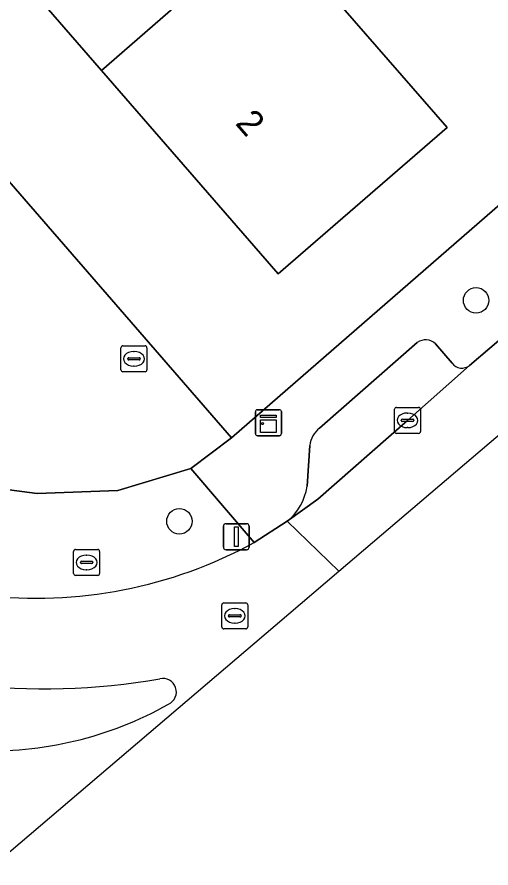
# Model space of a CAD drawing. Extents: x 155887 to 156869, y 383880 to 384678.
# Drawn here: x 156395.65 to 156413.9, y 383945.21 to 383977.95 of the extents above; entities that cross this region are included whole.
import ezdxf

# ---------------------------------------------------------------- set-up
doc = ezdxf.new("R2010")
doc.units = 0
for name, color, linetype in [('IMGEO_Berm_groen', 7, 'Continuous'), ('IMGEO_Boom', 7, 'Continuous'), ('IMGEO_Brandkraan', 7, 'Continuous'), ('IMGEO_Erf', 7, 'Continuous'), ('IMGEO_Kast', 7, 'Continuous'), ('IMGEO_Kolk', 7, 'Continuous'), ('IMGEO_Lichtmast', 7, 'Continuous'), ('IMGEO_Pand', 7, 'Continuous'), ('IMGEO_Pand_nummerreeks', 7, 'Continuous'), ('IMGEO_Parkeervlak_open', 7, 'Continuous'), ('IMGEO_Rijbaan_lokaal_gesloten', 7, 'Continuous'), ('IMGEO_Rioolput', 7, 'Continuous'), ('IMGEO_Verkeerseiland_open', 7, 'Continuous'), ('IMGEO_Voetpad_open', 7, 'Continuous')]:
    doc.layers.add(name, color=color, linetype=linetype)

msp = doc.modelspace()

# ---------------------------------------------------------------- linework, layer by layer
at = {"layer": 'IMGEO_Berm_groen'}
msp.add_lwpolyline([(156404.777, 383957.73), (156402.343, 383960.577), (156399.536, 383959.735), (156396.435, 383959.619), (156384.17, 383961.221), (156383.842, 383958.663), (156383.701, 383957.674)], dxfattribs=at)
msp.add_arc((156396.408, 383972.994), 17.408, 263.2684, 298.7369, dxfattribs=at)
at = {"layer": 'IMGEO_Boom'}
for centre in [(156413.326, 383967.047), (156401.904, 383958.547)]:
    msp.add_circle(centre, 0.489, dxfattribs=at)
at = {"layer": 'IMGEO_Brandkraan'}
for p, q in [((156399.655, 383964.372), (156399.655, 383965.224)), ((156399.73, 383965.298), (156400.582, 383965.298)), ((156400.656, 383965.224), (156400.656, 383964.372)), ((156399.957, 383964.841), (156400.355, 383964.841)), ((156400.143, 383965.078), (156400.168, 383965.078)), ((156399.914, 383964.792), (156399.914, 383964.804)), ((156400.352, 383964.755), (156399.954, 383964.755)), ((156400.166, 383964.518), (156400.141, 383964.518)), ((156400.398, 383964.804), (156400.398, 383964.792)), ((156400.582, 383964.298), (156399.73, 383964.298))]:
    msp.add_line(p, q, dxfattribs=at)
for points in [[(156399.655, 383964.372), (156399.655, 383965.224)], [(156399.73, 383965.298), (156400.582, 383965.298)], [(156400.656, 383965.224), (156400.656, 383964.372)], [(156400.582, 383964.298), (156399.73, 383964.298)]]:
    msp.add_lwpolyline(points, dxfattribs=at)
for centre, radius, start, end in [((156399.732, 383965.222), 0.0765, 91.552, 178.448), ((156399.732, 383965.222), 0.0765, 91.552, 178.448), ((156400.58, 383965.222), 0.0765, 1.552, 88.448), ((156400.58, 383965.222), 0.0765, 1.552, 88.448), ((156399.954, 383964.801), 0.0403, 85.8775, 175.7526), ((156400.359, 383964.803), 0.0386, 1.7309, 96.639), ((156399.951, 383964.791), 0.0366, 178.938, 274.7102), ((156400.355, 383964.798), 0.043, 264.8664, 352.4533), ((156399.732, 383964.374), 0.0765, 181.552, 268.448), ((156399.732, 383964.374), 0.0765, 181.552, 268.448), ((156400.58, 383964.374), 0.0765, 271.552, 358.448), ((156400.58, 383964.374), 0.0765, 271.552, 358.448)]:
    msp.add_arc(centre, radius, start, end, dxfattribs=at)
for centre, major_axis, ratio, start_param, end_param in [((156400.142, 383964.798), (-0.387, 0.002), 0.722429, 4.712389, 7.853982), ((156400.167, 383964.798), (-0.39, 0.002), 0.717154, 1.570796, 4.712389)]:
    msp.add_ellipse(centre, major_axis=major_axis, ratio=ratio, start_param=start_param, end_param=end_param, dxfattribs=at)
at = {"layer": 'IMGEO_Erf'}
for points in [[(156370.715, 384000), (156403.914, 383961.759), (156447.9, 384000), (156450.32, 384002.104), (156447.442, 384005.351), (156442.777, 384001.297), (156441.285, 384000), (156438.193, 383997.312), (156433.738, 383993.441), (156429.134, 383989.439), (156424.53, 383985.438), (156419.998, 383981.499), (156412.635, 383989.948), (156417.427, 383994.112), (156418.816, 383992.513), (156418.883, 383992.436), (156423.241, 383996.223), (156427.589, 384000), (156427.713, 384000.108), (156426.24, 384001.807), (156424.143, 384004.225), (156428.841, 384008.298), (156430.874, 384005.835), (156435.4, 384009.769)], [(156385.457, 384009.21), (156386.455, 384008.063), (156390.586, 384003.317), (156393.473, 384000), (156394.953, 383998.297), (156399.218, 383993.391), (156403.482, 383988.485), (156407.747, 383983.58), (156410.555, 383980.349), (156408.201, 383978.302), (156412.209, 383973.692), (156405.709, 383968.065), (156398.902, 383975.896), (156394.637, 383980.801), (156390.373, 383985.707), (156386.108, 383990.613), (156381.844, 383995.518), (156377.948, 384000), (156377.617, 384000.38), (156373.325, 384005.318), (156369.161, 384001.79)]]:
    msp.add_lwpolyline(points, dxfattribs=at)
at = {"layer": 'IMGEO_Kast'}
for p, q in [((156404.829, 383961.915), (156404.829, 383962.756)), ((156404.829, 383962.756), (156404.829, 383961.915)), ((156404.904, 383962.84), (156405.745, 383962.84)), ((156405.745, 383962.84), (156404.904, 383962.84)), ((156405.829, 383962.765), (156405.829, 383961.924)), ((156405.829, 383961.924), (156405.829, 383962.765)), ((156405.754, 383961.84), (156404.913, 383961.84)), ((156404.913, 383961.84), (156405.754, 383961.84))]:
    msp.add_line(p, q, dxfattribs=at)
for points in [[(156405.024, 383962.63), (156405.624, 383962.63), (156405.624, 383962.545), (156405.024, 383962.545), (156405.024, 383962.63)], [(156405.024, 383962.455), (156405.624, 383962.455), (156405.624, 383961.966), (156405.024, 383961.966), (156405.024, 383962.455)]]:
    msp.add_lwpolyline(points, dxfattribs=at)
msp.add_circle((156405.108, 383962.304), 0.0377, dxfattribs=at)
for centre, start, end in [((156404.907, 383962.762), 92.4484, 184.2845), ((156404.907, 383962.762), 92.4484, 184.2845), ((156405.751, 383962.762), 2.4484, 94.2845), ((156405.751, 383962.762), 2.4484, 94.2845), ((156404.907, 383961.918), 182.4484, 274.2845), ((156404.907, 383961.918), 182.4484, 274.2845), ((156405.751, 383961.918), 272.4484, 4.2845), ((156405.751, 383961.918), 272.4484, 4.2845)]:
    msp.add_arc(centre, 0.0779, start, end, dxfattribs=at)
at = {"layer": 'IMGEO_Kolk'}
for p, q in [((156410.187, 383962.005), (156410.187, 383962.857)), ((156410.262, 383962.931), (156411.114, 383962.931)), ((156411.188, 383962.857), (156411.188, 383962.005)), ((156410.675, 383962.711), (156410.7, 383962.711)), ((156410.446, 383962.425), (156410.446, 383962.437)), ((156410.884, 383962.388), (156410.486, 383962.388)), ((156410.489, 383962.474), (156410.887, 383962.474)), ((156410.93, 383962.437), (156410.93, 383962.425)), ((156411.114, 383961.931), (156410.262, 383961.931)), ((156410.698, 383962.151), (156410.673, 383962.151))]:
    msp.add_line(p, q, dxfattribs=at)
for points in [[(156410.187, 383962.005), (156410.187, 383962.857)], [(156410.262, 383962.931), (156411.114, 383962.931)], [(156411.188, 383962.857), (156411.188, 383962.005)], [(156411.114, 383961.931), (156410.262, 383961.931)]]:
    msp.add_lwpolyline(points, dxfattribs=at)
for centre, radius, start, end in [((156410.264, 383962.855), 0.0765, 91.552, 178.448), ((156410.264, 383962.855), 0.0765, 91.552, 178.448), ((156411.112, 383962.855), 0.0765, 1.552, 88.448), ((156411.112, 383962.855), 0.0765, 1.552, 88.448), ((156410.486, 383962.434), 0.0403, 85.8775, 175.7526), ((156410.483, 383962.424), 0.0366, 178.938, 274.7102), ((156410.887, 383962.431), 0.043, 264.8664, 352.4533), ((156410.891, 383962.436), 0.0386, 1.7309, 96.639), ((156410.264, 383962.007), 0.0765, 181.552, 268.448), ((156410.264, 383962.007), 0.0765, 181.552, 268.448), ((156411.112, 383962.007), 0.0765, 271.552, 358.448), ((156411.112, 383962.007), 0.0765, 271.552, 358.448)]:
    msp.add_arc(centre, radius, start, end, dxfattribs=at)
for centre, major_axis, ratio, start_param, end_param in [((156410.674, 383962.431), (-0.387, 0.002), 0.722429, 4.712389, 7.853982), ((156410.699, 383962.431), (-0.39, 0.002), 0.717154, 1.570796, 4.712389)]:
    msp.add_ellipse(centre, major_axis=major_axis, ratio=ratio, start_param=start_param, end_param=end_param, dxfattribs=at)
at = {"layer": 'IMGEO_Lichtmast'}
for p, q in [((156403.6, 383957.555), (156403.6, 383958.355)), ((156403.6, 383958.355), (156403.6, 383957.555)), ((156403.7, 383958.455), (156404.49, 383958.455)), ((156404.49, 383958.455), (156403.7, 383958.455)), ((156404.59, 383958.355), (156404.59, 383957.555)), ((156404.59, 383957.555), (156404.59, 383958.355)), ((156404.49, 383957.455), (156403.7, 383957.455)), ((156403.7, 383957.455), (156404.49, 383957.455))]:
    msp.add_line(p, q, dxfattribs=at)
msp.add_lwpolyline([(156404.02, 383958.33), (156404.17, 383958.33), (156404.17, 383957.58), (156404.02, 383957.58), (156404.02, 383958.33)], dxfattribs=at)
for centre, start, end in [((156403.7, 383958.355), 90, 180), ((156403.7, 383958.355), 90, 180), ((156404.49, 383958.355), 0, 90), ((156404.49, 383958.355), 360, 90), ((156403.7, 383957.555), 180, 270), ((156403.7, 383957.555), 180, 270), ((156404.49, 383957.555), 270, 0), ((156404.49, 383957.555), 270, 0)]:
    msp.add_arc(centre, 0.1, start, end, dxfattribs=at)
at = {"layer": 'IMGEO_Pand'}
for points in [[(156394.637, 383980.801), (156398.902, 383975.896), (156407.747, 383983.58), (156403.482, 383988.485)], [(156407.747, 383983.58), (156398.902, 383975.896), (156405.709, 383968.065), (156412.209, 383973.692), (156408.201, 383978.302), (156410.555, 383980.349)]]:
    msp.add_lwpolyline(points, close=True, dxfattribs=at)
at = {"layer": 'IMGEO_Parkeervlak_open'}
for points in [[(156411.058, 383965.425), (156407.295, 383962.13)], [(156412.399, 383964.625), (156411.767, 383965.379)], [(156410.688, 383962.43), (156413.073, 383964.545)], [(156406.056, 383958.55), (156407.237, 383959.396), (156410.688, 383962.43)], [(156406.92, 383961.464), (156406.818, 383959.894)]]:
    msp.add_lwpolyline(points, dxfattribs=at)
for centre, radius, start, end in [((156411.384, 383964.962), 0.566, 47.4343, 125.1414), ((156412.775, 383964.914), 0.474, 217.5284, 308.9336), ((156407.947, 383961.324), 1.037, 128.9906, 172.2449), ((156404.712, 383960.2), 2.129, 309.1692, 351.7274)]:
    msp.add_arc(centre, radius, start, end, dxfattribs=at)
at = {"layer": 'IMGEO_Rijbaan_lokaal_gesloten'}
for points in [[(156408.038, 383956.623), (156453.209, 383995.074), (156451.887, 383996.593), (156454.537, 383998.855), (156455.868, 383997.337), (156503.1, 384037.543)], [(156467.977, 384012.246), (156460.629, 384005.865), (156457.111, 384002.781), (156453.905, 384000), (156447.548, 383994.486), (156442.487, 383990.093), (156430.123, 383979.343), (156427.914, 383977.4), (156424.433, 383974.388), (156421.6, 383971.962), (156414.632, 383965.88), (156413.073, 383964.545), (156410.688, 383962.43), (156407.237, 383959.396), (156406.056, 383958.55), (156408.038, 383956.623)], [(156394.629, 383945.209), (156405.586, 383954.536), (156408.038, 383956.623), (156406.056, 383958.55), (156404.777, 383957.73)]]:
    msp.add_lwpolyline(points, dxfattribs=at)
for centre, radius, start, end in [((156396.408, 383972.994), 17.408, 263.2684, 298.7369), ((156396.684, 383978.256), 26.156, 263.4152, 279.8369), ((156401.272, 383951.982), 0.516, 294.3129, 103.2982), ((156394.656, 383963.612), 13.894, 267.4517, 299.4373)]:
    msp.add_arc(centre, radius, start, end, dxfattribs=at)
at = {"layer": 'IMGEO_Rioolput'}
for p, q in [((156397.833, 383956.538), (156397.833, 383957.39)), ((156397.908, 383957.464), (156398.76, 383957.464)), ((156398.834, 383957.39), (156398.834, 383956.538)), ((156398.092, 383956.958), (156398.092, 383956.97)), ((156398.135, 383957.007), (156398.533, 383957.007)), ((156398.321, 383957.244), (156398.346, 383957.244)), ((156398.576, 383956.97), (156398.576, 383956.958)), ((156398.53, 383956.921), (156398.132, 383956.921)), ((156398.344, 383956.684), (156398.319, 383956.684)), ((156398.76, 383956.464), (156397.908, 383956.464)), ((156403.537, 383954.483), (156403.537, 383955.335)), ((156403.612, 383955.409), (156404.464, 383955.409)), ((156404.538, 383955.335), (156404.538, 383954.483)), ((156404.025, 383955.189), (156404.05, 383955.189)), ((156403.796, 383954.903), (156403.796, 383954.915)), ((156404.234, 383954.866), (156403.836, 383954.866)), ((156403.839, 383954.952), (156404.237, 383954.952)), ((156404.28, 383954.915), (156404.28, 383954.903)), ((156404.464, 383954.409), (156403.612, 383954.409)), ((156404.048, 383954.629), (156404.023, 383954.629))]:
    msp.add_line(p, q, dxfattribs=at)
for points in [[(156397.833, 383956.538), (156397.833, 383957.39)], [(156397.908, 383957.464), (156398.76, 383957.464)], [(156398.834, 383957.39), (156398.834, 383956.538)], [(156398.76, 383956.464), (156397.908, 383956.464)], [(156403.537, 383954.483), (156403.537, 383955.335)], [(156403.612, 383955.409), (156404.464, 383955.409)], [(156404.538, 383955.335), (156404.538, 383954.483)], [(156404.464, 383954.409), (156403.612, 383954.409)]]:
    msp.add_lwpolyline(points, dxfattribs=at)
for centre, radius, start, end in [((156397.91, 383957.388), 0.0765, 91.552, 178.448), ((156397.91, 383957.388), 0.0765, 91.552, 178.448), ((156398.758, 383957.388), 0.0765, 1.552, 88.448), ((156398.758, 383957.388), 0.0765, 1.552, 88.448), ((156398.132, 383956.967), 0.0403, 85.8775, 175.7526), ((156398.537, 383956.969), 0.0386, 1.7309, 96.639), ((156398.129, 383956.957), 0.0366, 178.938, 274.7102), ((156398.533, 383956.964), 0.043, 264.8664, 352.4533), ((156397.91, 383956.54), 0.0765, 181.552, 268.448), ((156397.91, 383956.54), 0.0765, 181.552, 268.448), ((156398.758, 383956.54), 0.0765, 271.552, 358.448), ((156398.758, 383956.54), 0.0765, 271.552, 358.448), ((156403.614, 383955.333), 0.0765, 91.552, 178.448), ((156403.614, 383955.333), 0.0765, 91.552, 178.448), ((156404.462, 383955.333), 0.0765, 1.552, 88.448), ((156404.462, 383955.333), 0.0765, 1.552, 88.448), ((156403.836, 383954.912), 0.0403, 85.8775, 175.7526), ((156403.833, 383954.902), 0.0366, 178.938, 274.7102), ((156404.237, 383954.909), 0.043, 264.8664, 352.4533), ((156404.241, 383954.914), 0.0386, 1.7309, 96.639), ((156403.614, 383954.485), 0.0765, 181.552, 268.448), ((156403.614, 383954.485), 0.0765, 181.552, 268.448), ((156404.462, 383954.485), 0.0765, 271.552, 358.448), ((156404.462, 383954.485), 0.0765, 271.552, 358.448)]:
    msp.add_arc(centre, radius, start, end, dxfattribs=at)
for centre, major_axis, ratio, start_param, end_param in [((156398.32, 383956.964), (-0.387, 0.002), 0.722429, 4.712389, 7.853982), ((156398.345, 383956.964), (-0.39, 0.002), 0.717154, 1.570796, 4.712389), ((156404.024, 383954.909), (-0.387, 0.002), 0.722429, 4.712389, 7.853982), ((156404.049, 383954.909), (-0.39, 0.002), 0.717154, 1.570796, 4.712389)]:
    msp.add_ellipse(centre, major_axis=major_axis, ratio=ratio, start_param=start_param, end_param=end_param, dxfattribs=at)
at = {"layer": 'IMGEO_Verkeerseiland_open'}
for centre, radius, start, end in [((156396.684, 383978.256), 26.156, 263.4152, 279.8369), ((156401.272, 383951.982), 0.516, 294.3129, 103.2982), ((156394.656, 383963.612), 13.894, 267.4517, 299.4373)]:
    msp.add_arc(centre, radius, start, end, dxfattribs=at)
at = {"layer": 'IMGEO_Voetpad_open'}
for points in [[(156493.397, 384034.33), (156493.619, 384034.523), (156496.069, 384036.641), (156494.617, 384038.319), (156499.442, 384042.575), (156498.182, 384043.649), (156452.547, 384004.012), (156450.32, 384002.104), (156447.9, 384000), (156403.914, 383961.759), (156402.343, 383960.577), (156404.777, 383957.73), (156406.056, 383958.55)], [(156376.206, 383962.213), (156378.318, 383961.954), (156382.185, 383961.48), (156384.17, 383961.221), (156396.435, 383959.619), (156399.536, 383959.735), (156402.343, 383960.577), (156403.914, 383961.759), (156370.715, 384000)], [(156413.073, 383964.545), (156414.632, 383965.88)], [(156407.295, 383962.13), (156411.058, 383965.425)], [(156411.767, 383965.379), (156412.399, 383964.625)], [(156406.818, 383959.894), (156406.92, 383961.464)]]:
    msp.add_lwpolyline(points, dxfattribs=at)
for centre, radius, start, end in [((156411.384, 383964.962), 0.566, 47.4343, 125.1414), ((156412.775, 383964.914), 0.474, 217.5284, 308.9336), ((156407.947, 383961.324), 1.037, 128.9906, 172.2449), ((156404.712, 383960.2), 2.129, 309.1692, 351.7274)]:
    msp.add_arc(centre, radius, start, end, dxfattribs=at)

# ---------------------------------------------------------------- texts
at = {"layer": 'IMGEO_Pand_nummerreeks'}
msp.add_text('2', height=1, rotation=310.9984, dxfattribs=at).set_placement((156404.025, 383973.843))

doc.saveas('drawing.dxf')
